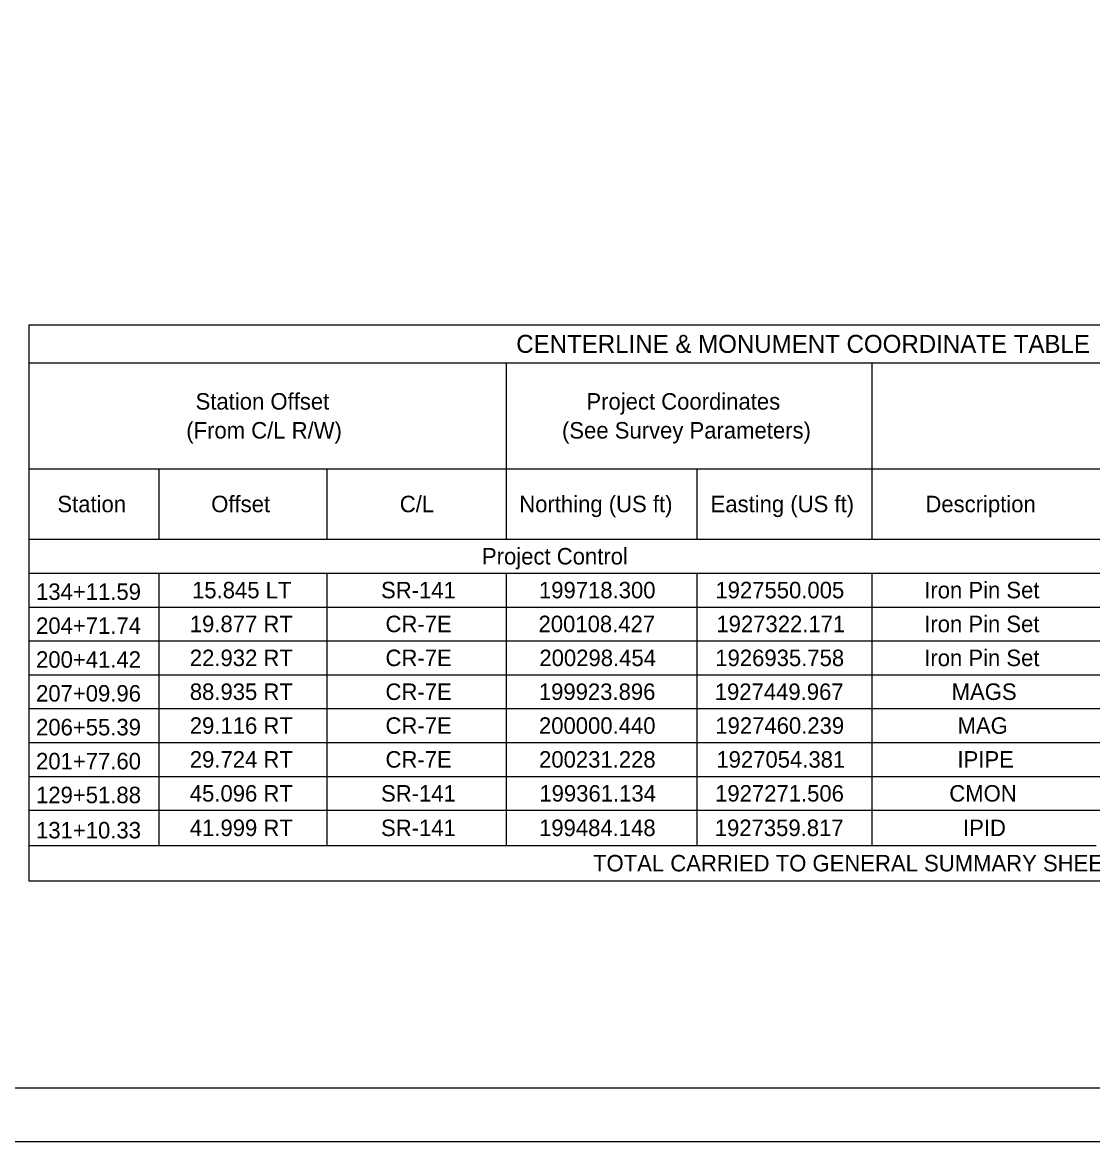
# Model space of a CAD drawing. Extents: x 0 to 34, y 0 to 22.
# Drawn here: x 17.48 to 27.47, y 0 to 10.45 of the extents above; entities that cross this region are included whole.
import ezdxf

# ---------------------------------------------------------------- set-up
doc = ezdxf.new("R2010")
doc.units = 0
for name, color, linetype in [('_CIVIL_CONSTRUCTION', 7, 'Continuous'), ('SG_X_Poles', 7, 'Continuous'), ('SH_Masking', 7, 'Continuous')]:
    doc.layers.add(name, color=color, linetype=linetype)

msp = doc.modelspace()

# ---------------------------------------------------------------- linework, layer by layer
at = {"layer": '_CIVIL_CONSTRUCTION'}
msp.add_lwpolyline([(1.5, 21.5), (33.5, 21.5), (33.5, 0.5), (1.5, 0.5)], close=True, dxfattribs=at)
at = {"layer": 'SG_X_Poles'}
for p, q in [((17.54, 7.627), (30.361, 7.627)), ((17.54, 7.627), (17.54, 4.359)), ((17.54, 7.271), (30.361, 7.271)), ((21.994, 7.271), (21.994, 5.624)), ((25.407, 7.271), (25.407, 5.624)), ((17.54, 6.283), (30.361, 6.283)), ((18.753, 6.283), (18.753, 5.624)), ((20.321, 6.283), (20.321, 5.624)), ((23.773, 6.283), (23.773, 5.624)), ((17.54, 5.624), (30.361, 5.624)), ((17.54, 5.308), (30.361, 5.308)), ((18.753, 5.308), (18.753, 4.359)), ((20.321, 5.308), (20.321, 4.359)), ((21.994, 5.308), (21.994, 4.359)), ((23.773, 5.308), (23.773, 4.359)), ((25.407, 5.308), (25.407, 4.359)), ((17.54, 4.992), (30.361, 4.992)), ((17.54, 4.675), (30.361, 4.675)), ((17.54, 4.359), (30.361, 4.359)), ((17.54, 4.359), (17.54, 4.043)), ((18.753, 4.359), (18.753, 4.043)), ((20.321, 4.359), (20.321, 4.043)), ((21.994, 4.359), (21.994, 4.043)), ((23.773, 4.359), (23.773, 4.043)), ((25.407, 4.359), (25.407, 4.043)), ((17.54, 4.043), (30.361, 4.043)), ((17.54, 4.043), (17.54, 2.435)), ((18.753, 4.043), (18.753, 2.765)), ((20.321, 4.043), (20.321, 2.765)), ((21.994, 4.043), (21.994, 2.765)), ((23.773, 4.043), (23.773, 2.765)), ((25.407, 4.043), (25.407, 2.765)), ((17.54, 3.727), (30.361, 3.727)), ((17.54, 3.41), (30.361, 3.41)), ((17.54, 3.094), (30.361, 3.094)), ((17.54, 2.765), (27.502, 2.765)), ((17.54, 2.435), (30.361, 2.435))]:
    msp.add_line(p, q, dxfattribs=at)
at = {"layer": 'SH_Masking'}
msp.add_lwpolyline([(0, 0), (34, 0), (34, 22), (0, 22)], close=True, dxfattribs=at)

# ---------------------------------------------------------------- texts
at = {"layer": 'SG_X_Poles'}
for s, height, p in [('CENTERLINE & MONUMENT COORDINATE TABLE', 0.168, (22.088, 7.365)), ('Station Offset', 0.154, (19.095, 6.835)), ('Project Coordinates', 0.154, (22.743, 6.835)), ('(From C/L R/W)', 0.154, (19.008, 6.565)), ('(See Survey Parameters)', 0.154, (22.515, 6.565)), ('Station', 0.154, (17.805, 5.877)), ('Offset', 0.154, (19.241, 5.877)), ('C/L', 0.154, (21.001, 5.877)), ('Northing (US ft)', 0.154, (22.116, 5.877)), ('Easting (US ft)', 0.154, (23.902, 5.877)), ('Description', 0.154, (25.907, 5.877)), ('Project Control', 0.154, (21.768, 5.389)), ('15.845 LT', 0.154, (19.062, 5.073)), ('SR-141', 0.154, (20.826, 5.073)), ('199718.300', 0.154, (22.3, 5.073)), ('1927550.005', 0.154, (23.947, 5.073)), ('Iron Pin Set', 0.154, (25.896, 5.073)), ('134+11.59', 0.154, (17.606, 5.058)), ('19.877 RT', 0.154, (19.041, 4.757)), ('CR-7E', 0.154, (20.868, 4.757)), ('200108.427', 0.154, (22.296, 4.757)), ('1927322.171', 0.154, (23.956, 4.757)), ('Iron Pin Set', 0.154, (25.896, 4.757)), ('204+71.74', 0.154, (17.606, 4.741)), ('Iron Pin Set', 0.154, (25.896, 4.44)), ('200+41.42', 0.154, (17.606, 4.425)), ('22.932 RT', 0.154, (19.041, 4.44)), ('CR-7E', 0.154, (20.868, 4.44)), ('200298.454', 0.154, (22.304, 4.44)), ('1926935.758', 0.154, (23.946, 4.44)), ('207+09.96', 0.154, (17.606, 4.109)), ('88.935 RT', 0.154, (19.041, 4.124)), ('CR-7E', 0.154, (20.868, 4.124)), ('199923.896', 0.154, (22.299, 4.124)), ('1927449.967', 0.154, (23.941, 4.124)), ('MAGS', 0.154, (26.152, 4.124)), ('206+55.39', 0.154, (17.606, 3.793)), ('29.116 RT', 0.154, (19.041, 3.808)), ('CR-7E', 0.154, (20.868, 3.808)), ('200000.440', 0.154, (22.3, 3.808)), ('1927460.239', 0.154, (23.946, 3.808)), ('MAG', 0.154, (26.207, 3.808)), ('201+77.60', 0.154, (17.606, 3.476)), ('29.724 RT', 0.154, (19.041, 3.492)), ('CR-7E', 0.154, (20.868, 3.492)), ('200231.228', 0.154, (22.301, 3.492)), ('1927054.381', 0.154, (23.956, 3.492)), ('IPIPE', 0.154, (26.206, 3.492)), ('129+51.88', 0.154, (17.606, 3.16)), ('45.096 RT', 0.154, (19.041, 3.175)), ('SR-141', 0.154, (20.826, 3.175)), ('199361.134', 0.154, (22.304, 3.175)), ('1927271.506', 0.154, (23.944, 3.175)), ('CMON', 0.154, (26.13, 3.175)), ('131+10.33', 0.154, (17.606, 2.831)), ('41.999 RT', 0.154, (19.041, 2.853)), ('SR-141', 0.154, (20.826, 2.853)), ('199484.148', 0.154, (22.301, 2.853)), ('1927359.817', 0.154, (23.941, 2.853)), ('IPID', 0.154, (26.258, 2.853)), ('TOTAL CARRIED TO GENERAL SUMMARY SHEET', 0.154, (22.805, 2.523))]:
    msp.add_text(s, height=height, dxfattribs=at).set_placement(p)

doc.saveas('drawing.dxf')
